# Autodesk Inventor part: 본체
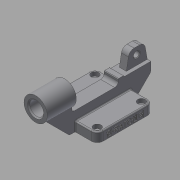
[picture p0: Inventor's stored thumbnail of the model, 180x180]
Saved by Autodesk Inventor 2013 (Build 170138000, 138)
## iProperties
Created: 2017-10
Part Number: 본체
Material: 일반
Document SubType Name: Modeling
Designer: mduedu
Density: 1 g/cm^3
Author: mduedu
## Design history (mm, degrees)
sketch "스케치1"
  geometry: L1 (0, 0)-(-90, 0); L2 (-90, 0)-(-90, 20); L3 (-90, 20)-(0, 20); L4 (0, 20)-(0, 0)
  constraints: 8 end point, 2 parallel, 1 horizontal, 1 perpendicular
  dimensions: "d0" = 90 distance of L2.end L3.end; "d2" = 20 distance of L1.end L2.end
extrude "돌출1" new body sketch "스케치1" stored distance "d3" = 12; taper "d4" = 0 deg
chamfer "모따기1" distance "d5" = 20; stored, may be unused: second distance "d6" = 2, angle "d7" = 45 deg
chamfer "모따기2" distance "d8" = 12; stored, may be unused: second distance "d9" = 2, angle "d10" = 45 deg
sketch "스케치2"
  geometry: L1 (5, 31)-(53, 31); L2 (53, 31)-(53, -19); L3 (53, -19)-(5, -19); L4 (5, -19)-(5, 31); L5 (58, 12)-(58, 0) reference; L6 (0, 0)-(0, 12) reference; 2 further points
  constraints: 8 end point, 2 parallel, 1 horizontal, 1 horizontal alignment, 1 midpoint, 1 perpendicular
  dimensions: "d11" = 5 distance between parallel lines of L2 L5; "d12" = 5 distance between parallel lines of L4 L6; "d13" = 50 distance of L1.end L2.end
extrude "돌출2" join sketch "스케치2" distance "d14" = 8; taper "d15" = 0 deg
sketch "스케치3"
  geometry: L1 (0, 20)-(-90, 20) reference; L2 (-28, 20)-(-68, 20); L3 (-68, 20)-(-68, 16); L4 (-68, 16)-(-28, 16); L5 (-28, 16)-(-28, 20); L6 (0, 20)-(0, 12) reference; 1 further point
  constraints: 8 end point, 2 parallel, 1 horizontal, 1 perpendicular, 1 point on line
  dimensions: "d16" = 40 distance of L2.start L2.end; "d18" = 4 distance of L4.end L2.start; "d19" = 28 distance between parallel lines of L5 L6
extrude "돌출3" cut sketch "스케치3" stored distance "d20" = 10; taper "d21" = 0 deg
sketch "스케치4"
  geometry: L1 (0, -16)-(12, -16) reference; L2 (0, 4)-(12, 4) reference; C1 r 10 at (6, 12); 2 further points
  constraints: 1 centre point, 1 midpoint, 1 vertical alignment
  dimensions: "d22" = 20 diameter of C1; "d23" = 8 distance from line of C1.centre L2
extrude "돌출4" join sketch "스케치4" distance "d24" = 25; taper "d25" = 0 deg
sketch "스케치5"
  geometry: L1 (0, 20)-(-28, 20) reference; L2 (0, 20)-(-18, 20); L3 (-18, 20)-(-18, 34); L4 (-18, 34)-(0, 34); L5 (0, 34)-(0, 20); 1 further point
  constraints: 8 end point, 2 parallel, 1 horizontal, 1 perpendicular
  dimensions: "d26" = 18 distance of L3.end L4.end; "d28" = 14 distance of L4.end L1.start
extrude "돌출5" join sketch "스케치5" stored distance "d29" = 6; taper "d30" = 0 deg
sketch "스케치6"
  geometry: L1 (28, -9)-(10, -9) reference; L2 (10, -9)-(10, -3) reference; L3 (10, -3)-(28, -3) reference; L4 (28, -3)-(28, 0) reference; L5 (0, 0)-(28, 0) reference; L6 (0, 0)-(0, -12) reference; L7 (28, -12)-(0, -12) reference; L8 (28, -12)-(28, -9) reference; L9 (28, -9)-(28, -3) reference; 1 further point
  node "투영된 루프1"
feature "면 기울기1" dims angle "d31" = 10 deg
feature "면 기울기2" dims angle "d32" = 10 deg, "d33" = 0
fillet "모깎기1" dims "d34" = 5
sketch "스케치7"
  geometry: L1 (-6.664, 34)-(-11.336, 34) reference; L2 (0, 20)-(-28, 20) reference; L3 (-9, 34)-(-9, 20); C1 r 2.5 at (-9, 28); 1 further point
  constraints: 2 end point, 2 point on line, 1 centre point, 1 midpoint, 1 perpendicular
  dimensions: "d35" = 5 diameter of C1; "d36" = 8 distance from line of L2 C1.centre
extrude "돌출6" cut sketch "스케치7" stored distance "d37" = 6; taper "d38" = 0 deg
sketch "스케치8"
  geometry: C1 r 6 at (6, 12); A1 r 10 centre (6, 12) between (12, 4) and (0, 4) reference; 1 further point
  constraints: 1 centre point, 1 coincident
  dimensions: "d39" = 12 diameter of C1
extrude "돌출7" cut sketch "스케치8" stored distance "d40" = 6; taper "d41" = 0 deg
chamfer "모따기3" distance "d42" = 1; stored, may be unused: second distance "d43" = 2, angle "d44" = 45 deg
chamfer "모따기4" distance "d45" = 0.5; stored, may be unused: second distance "d46" = 2, angle "d47" = 45 deg
fillet "모깎기2" dims "d48" = 2, "d49" = 3
fillet "모깎기3" dims "d50" = 5
fillet "모깎기4" dims "d51" = 3
sketch "스케치9"
  geometry: L1 (0, 12)-(0, 0) reference; L2 (0, 12)-(5, 12); L3 (5, 12)-(5, 0); L4 (5, 0)-(0, 0); L5 (0, 0)-(0, 12); 1 further point
  constraints: 8 end point, 2 parallel, 1 horizontal, 1 perpendicular
  dimensions: "d52" = 5 distance of L1.start L2.end
extrude "돌출8" join sketch "스케치9" distance "d53" = 1; taper "d54" = 0 deg
fillet "모깎기5" dims "d55" = 0.5
sketch "스케치10"
  geometry: A1 r 5 centre (10, 14) between (10, 19) and (5, 14) reference; A2 r 5 centre (48, 14) between (53, 14) and (48, 19) reference; A3 r 5 centre (48, -26) between (48, -31) and (53, -26) reference; A4 r 5 centre (10, -26) between (5, -26) and (10, -31) reference; 5 further points
  constraints: 4 coincident
sketch "스케치11"
  geometry: A1 r 5 centre (10, 14) between (10, 19) and (5, 14) reference; A2 r 5 centre (48, 14) between (53, 14) and (48, 19) reference; A3 r 5 centre (48, -26) between (48, -31) and (53, -26) reference; A4 r 5 centre (10, -26) between (5, -26) and (10, -31) reference; A5 r 5 centre (10, 14) between (10, 19) and (5, 14) reference; 4 further points
  constraints: 4 coincident
hole "구멍1" sketch "스케치11" at (10, 14), (48, 14), (48, -26), (10, -26) diameter "d56" = 3.4; stored, may be unused: countersink angle "d60" = 90 deg, drill point angle "d62" = 0 deg; dims "d57" = 6, "d58" = 6.5, "d59" = 3.4, "d61" = 8
fillet "모깎기6" dims "d63" = 1
fillet "모깎기7" dims "d64" = 1
sketch "스케치12"
  geometry: L1 (0, 0)-(0, 7) reference; L2 (38, 7)-(38, 0) reference; L3 (0, 3.5)-(38, 3.5); 3 further points
  constraints: 3 midpoint, 2 end point, 1 coincident, 1 other
feature "엠보싱1" sketch "스케치12" dims "d0" = 90, "d2" = 20, "d65" = 0.5, "d66" = 0
node "솔리드1"
